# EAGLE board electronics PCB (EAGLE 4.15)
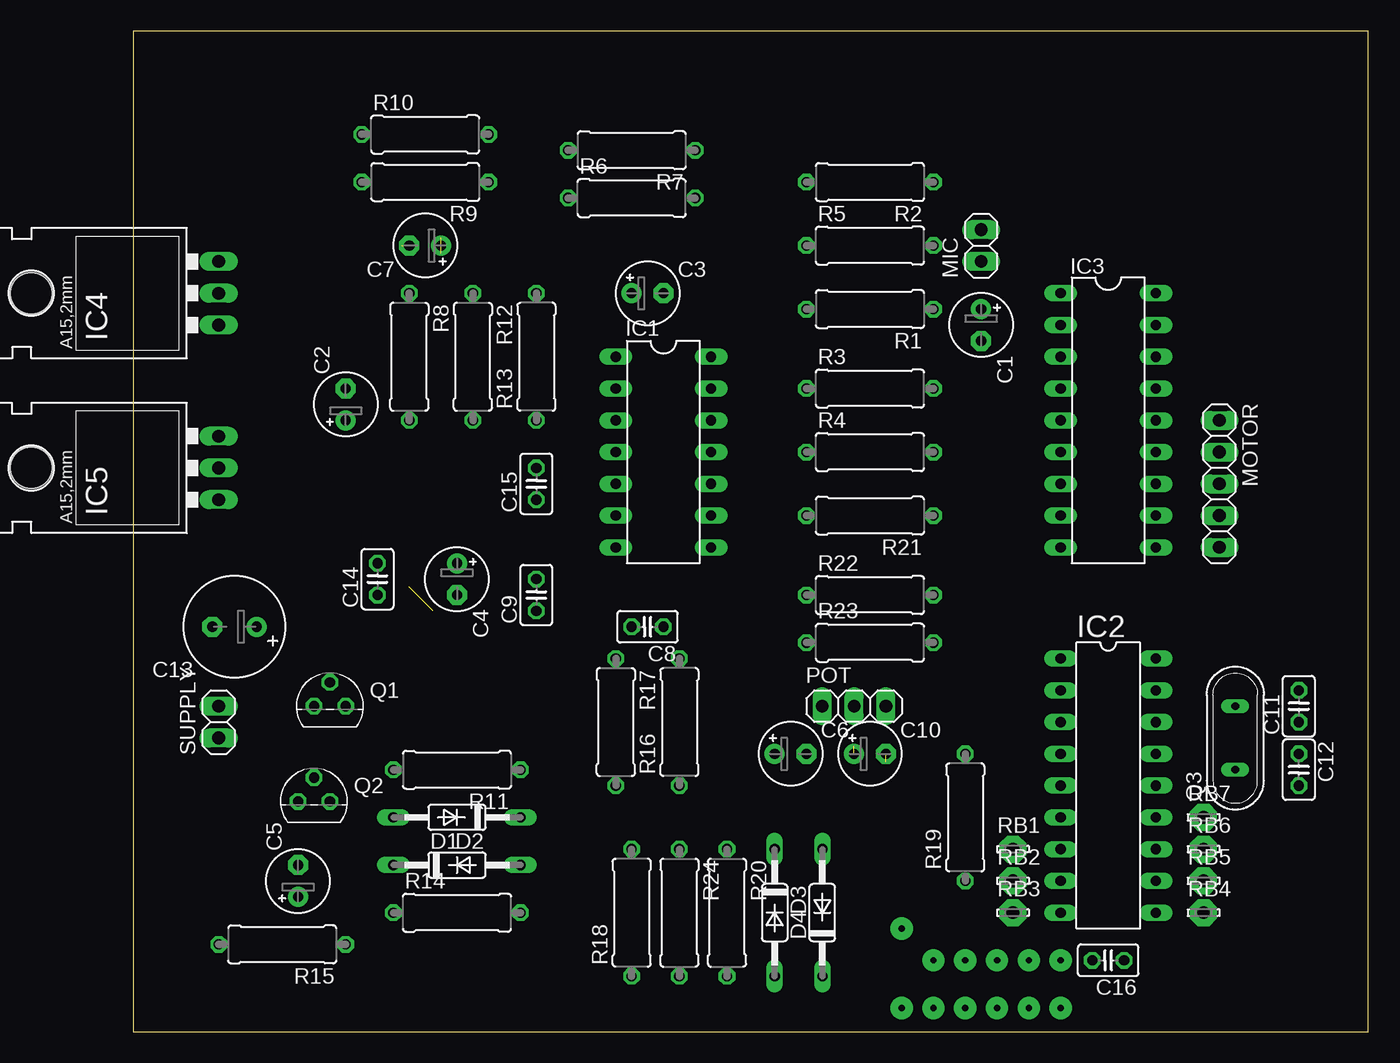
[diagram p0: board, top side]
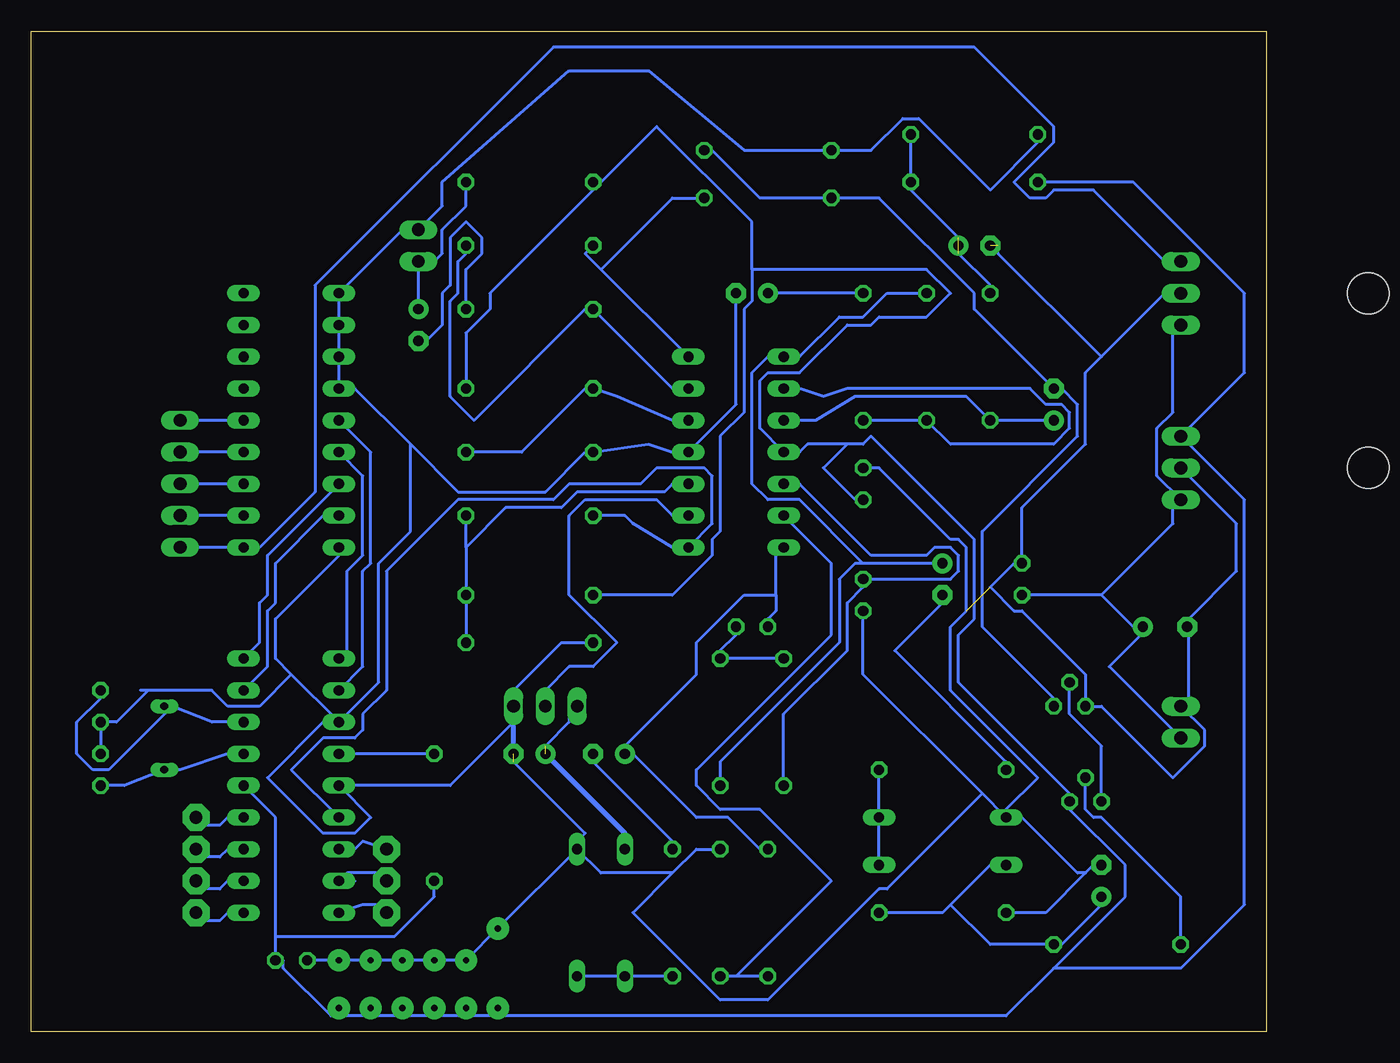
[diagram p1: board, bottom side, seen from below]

Size 98.73 x 80 mm. Coordinates in mm from the lower left corner, seen from the top.
Outline: 0,0 98.73,0 98.73,80 0,80 0,0
Copper layers (1*16): Top 0.035mm / dielectric 1.5mm / Bottom 0.035mm
Design rules "default": minimum track width 10mil, minimum drill 24mil, track to track 8mil, track to pad 8mil, pad to pad 8mil, via to via 8mil, smd to smd 8mil, copper to edge 40mil, drill to drill 8mil, minimum pad ring 10mil, minimum via ring 8mil, stop-mask expansion 4mil, vias tented up to drill 0mil, thermal gap 10mil

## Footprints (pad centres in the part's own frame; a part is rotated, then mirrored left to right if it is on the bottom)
E2,5-5 = drill 0.813 pad 1.6 round: + -1.27,0 | drill 0.813 pad 1.6 octagon: - 1.27,0
C025-025X050 = drill 0.813 octagon: 1 -1.27,0; 2 1.27,0
E3,5-8 = drill 0.813 pad 1.6 round: + -1.778,0 | drill 0.813 pad 1.6 octagon: - 1.778,0
DO35-10 = drill 0.813 long: A 5.08,0; C -5.08,0
DIL14 = drill 0.813 long: 1 -7.62,-3.81; 2 -5.08,-3.81; 3 -2.54,-3.81; 4 0,-3.81; 5 2.54,-3.81; 6 5.08,-3.81; 7 7.62,-3.81; 8 7.62,3.81; 9 5.08,3.81; 10 2.54,3.81; 11 0,3.81; 12 -2.54,3.81; 13 -5.08,3.81; 14 -7.62,3.81
DIL18 = drill 0.813 long: 1 -10.16,-3.81; 2 -7.62,-3.81; 3 -5.08,-3.81; 4 -2.54,-3.81; 5 0,-3.81; 6 2.54,-3.81; 7 5.08,-3.81; 8 7.62,-3.81; 9 10.16,-3.81; 10 10.16,3.81; 11 7.62,3.81; 12 5.08,3.81; 13 2.54,3.81; 14 0,3.81; 15 -2.54,3.81; 16 -5.08,3.81; 17 -7.62,3.81; 18 -10.16,3.81
78XXL = drill 1.016 long: GND 0,-3.81; IN -2.54,-3.81; OUT 2.54,-3.81 | hole 3.302: 0,11.176
1X02 = drill 1.016 long: 1 -1.27,0; 2 1.27,0
1X05 = drill 1.016 long: 1 -5.08,0; 2 -2.54,0; 3 0,0; 4 2.54,0; 5 5.08,0
1X03 = drill 1.016 long: 1 -2.54,0; 2 0,0; 3 2.54,0
TO92 = drill 0.813 octagon: 1 1.27,0; 2 0,1.905; 3 -1.27,0
QS = drill 0.61 long: 1 -2.54,0; 2 2.54,0
0309/10 = drill 0.813 octagon: 1 -5.08,0; 2 5.08,0
LSP10 = drill 1.016 pad 2.159 octagon: MP 0,0

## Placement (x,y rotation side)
C1  4.7u  [E2,5-5]  67.78,56.51 270 top
C2  10u  [E2,5-5]  16.98,50.16 90 top
C3  22u  [E2,5-5]  41.11,59.05 0 top
C4  22u  [E2,5-5]  25.87,36.19 270 top
C5  47u  [E2,5-5]  13.17,12.06 90 top
C6  22u  [E2,5-5]  52.54,22.22 0 top
C7  100u  [E2,5-5]  23.33,62.86 180 top
C8  22n  [C025-025X050]  41.11,32.38 180 top
C9  10n  [C025-025X050]  32.22,34.92 90 top
C10  2.2u  [E2,5-5]  58.89,22.22 0 top
C11  22n  [C025-025X050]  93.18,26.03 90 top
C12  22n  [C025-025X050]  93.18,20.95 270 top
C13  100u/65V  [E3,5-8]  8.09,32.38 180 top
C14  100n  [C025-025X050]  19.52,36.19 90 top
C15  100n  [C025-025X050]  32.22,43.81 90 top
C16  100n  [C025-025X050]  77.94,5.71 180 top
D1  1N4148  [DO35-10]  25.87,13.33 0 top
D2  1N4148  [DO35-10]  25.87,17.14 180 top
D3  1N4148  [DO35-10]  51.27,9.52 270 top
D4  1N4148  [DO35-10]  55.08,9.52 90 top
IC1  LM324N  [DIL14]  42.38,46.35 270 top
IC2  PIC16F84A  [DIL18]  77.94,19.68 270 top
IC3  ULN2803A  [DIL18]  77.94,48.89 270 top
IC4  [78XXL]  3.01,59.05 90 top
IC5  [78XXL]  3.01,45.08 90 top
MIC  [1X02]  67.78,62.86 90 top
MOTOR  [1X05]  86.83,43.81 270 top
POT  [1X03]  57.62,26.03 0 top
Q1  2N3904  [TO92]  15.71,26.03 0 top
Q2  2N3904  [TO92]  14.44,18.41 0 top
Q3  4MHz  [QS]  88.1,23.49 90 top
R1  10k  [0309/10]  58.89,57.78 180 top
R2  2k2  [0309/10]  58.89,67.94 180 top
R3  6k8  [0309/10]  58.89,51.43 0 top
R4  6k8  [0309/10]  58.89,46.35 0 top
R5  var  [0309/10]  58.89,62.86 0 top
R6  180k  [0309/10]  39.84,66.67 0 top
R7  47k  [0309/10]  39.84,70.48 180 top
R8  1M  [0309/10]  22.06,53.97 270 top
R9  100k  [0309/10]  23.33,67.94 180 top
R10  100k  [0309/10]  23.33,71.75 0 top
R11  5k6  [0309/10]  25.87,20.95 180 top
R12  27k  [0309/10]  27.14,53.97 270 top
R13  560  [0309/10]  32.22,53.97 90 top
R14  100k  [0309/10]  25.87,9.52 0 top
R15  10k  [0309/10]  11.9,6.98 180 top
R16  47k  [0309/10]  43.65,24.76 90 top
R17  47k  [0309/10]  38.57,24.76 270 top
R18  5k6  [0309/10]  39.84,9.52 90 top
R19  10k  [0309/10]  66.51,17.14 90 top
R20  560  [0309/10]  47.46,9.52 270 top
R21  270k  [0309/10]  58.89,41.27 180 top
R22  180k  [0309/10]  58.89,34.92 0 top
R23  4k7  [0309/10]  58.89,31.11 0 top
R24  100k  [0309/10]  43.65,9.52 270 top
RB1  LSP10  [LSP10]  70.32,14.6 0 top
RB2  LSP10  [LSP10]  70.32,12.06 0 top
RB3  LSP10  [LSP10]  70.32,9.52 0 top
RB4  LSP10  [LSP10]  85.56,9.52 0 top
RB5  LSP10  [LSP10]  85.56,12.06 0 top
RB6  LSP10  [LSP10]  85.56,14.6 0 top
RB7  LSP10  [LSP10]  85.56,17.14 0 top
SUPPLY  [1X02]  6.82,24.76 90 top

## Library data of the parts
C1-C16 R1-R24 = rcl
D1-D4 = diode
IC1 = linear
IC2 = microchip-2
IC3 = uln-udn
IC4 IC5 = v-reg
MIC MOTOR POT SUPPLY = pinhead
Q1 Q2 = transistor-npn
Q3 = special
RB1-RB7 = solpad

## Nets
+5V: C15.1 C16.1 IC1.4 IC2.14 IC5.OUT Q2.1 R2.2 R3.2 R9.2 R19.1 R22.1
+12V: IC3.10 IC4.OUT MOTOR.5
GND: C3.- C5.- C7.- C9.1 C10.- C11.1 C12.1 C13.- C14.2 C15.2 C16.2 D2.A D4.A IC1.11 IC2.3 IC2.5 IC3.1 IC3.2 IC3.3 IC3.4 IC3.9 IC4.GND IC5.GND MIC.2 POT.3 Q1.3 R4.1 R7.2 R10.1 R14.1 R23.1 R24.1 SUPPLY.2
N$1: C1.+ MIC.1 R2.1
N$2: C7.+ R8.1 R9.1 R10.2
N$3: C3.+ R13.2
N$4: C4.- R11.2
N$5: C8.1 R16.2 R17.1
N$6: IC1.6 R18.1 R24.2
N$7: C1.- R1.1
N$8: IC1.13 R1.2 R5.2
N$9: C4.+ IC1.1 R12.1 R16.1
N$10: IC1.12 R3.1 R4.2
N$11: IC1.14 R5.1 R6.2
N$12: C2.- Q1.1 R6.1 R7.1
N$13: C2.+ IC1.3 R8.2
N$14: C9.2 IC1.5 R17.2
N$15: IC1.2 R12.2 R13.1
N$16: D1.A D2.C R11.1
N$17: C5.+ D1.C R14.2 R15.1
N$18: Q2.2 R15.2
N$19: C6.+ C8.2 IC1.7 R18.2
N$20: Q1.2 Q2.3
N$21: C6.- R20.1
N$22: D3.A D4.C R20.2
N$23: C10.+ D3.C POT.1
N$24: IC1.9 POT.2
N$25: IC1.10 R21.1 R22.2 R23.2
N$26: IC1.8 IC2.6 R21.2
N$27: IC2.7 RB1.MP
N$28: IC2.8 RB2.MP
N$29: IC2.9 RB3.MP
N$30: IC2.10 RB4.MP
N$31: IC2.11 RB5.MP
N$32: IC2.12 RB6.MP
N$33: IC2.13 RB7.MP
N$34: IC2.2 IC3.5
N$35: IC2.1 IC3.6
N$36: IC2.18 IC3.7
N$37: IC2.17 IC3.8
N$38: IC3.11 MOTOR.4
N$39: IC3.12 MOTOR.3
N$40: IC3.13 MOTOR.2
N$41: IC3.14 MOTOR.1
N$42: C11.2 IC2.16 Q3.2
N$43: C12.2 IC2.15 Q3.1
N$45: IC2.4 R19.2
N$46: C13.+ C14.1 IC4.IN IC5.IN SUPPLY.1

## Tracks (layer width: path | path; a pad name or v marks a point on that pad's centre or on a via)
+5V
  Bottom 0.254: 41.11,60.96 41.11,64.77 48.73,72.38 53.18,67.94 R2.2 53.81,67.3 62.07,59.05 62.07,57.78 63.97,55.88 R3.2 | 41.11,60.96 41.11,58.41 41.75,57.78 41.75,49.53 43.65,47.62 43.65,40 44.29,39.37 44.29,38.1 47.46,34.92 R22.1 | R9.2 10.63,67.94 1.74,59.05 1.74,52.7 IC5.OUT 1.74,42.54 1.74,10.16 6.82,5.08 16.98,5.08 | 79.21,7.62 79.21,17.14 IC2.14 | 79.21,7.62 C16.1 78.58,5.71 78.58,5.08 74.77,1.27 20.79,1.27 16.98,5.08 | 79.21,7.62 69.69,7.62 66.51,10.79 R19.1 | 33.49,46.98 36.67,46.98 37.3,46.35 IC1.4 40.48,48.26 40.48,52.07 39.84,52.7 37.3,52.7 33.49,56.51 31.58,56.51 30.95,57.15 27.14,57.15 25.23,59.05 27.14,60.96 41.11,60.96 | 33.49,46.98 32.22,46.98 31.58,47.62 23.33,39.37 23.33,33.02 24.6,31.74 24.6,27.93 15.71,19.04 Q2.1 15.71,17.77 11.26,13.33 11.26,10.79 16.98,5.08 | 33.49,46.98 35.4,45.08 32.86,42.54 C15.1
+12V
  Bottom 0.254: MOTOR.5 IC3.10 80.48,38.73 76.03,43.18 76.03,59.69 56.98,78.73 23.33,78.73 16.98,72.38 16.98,71.11 20.15,67.94 18.88,66.67 17.61,66.67 16.98,67.3 13.8,67.3 8.09,61.59 IC4.OUT
GND  (via drill 0.5 pad 1.78)  (3 unrouted)
  Bottom 0.254: R10.1 18.25,71.11 22.06,67.3 27.77,73.02 29.04,73.02 31.58,70.48 R7.2 41.75,70.48 49.37,76.83 55.72,76.83 65.88,67.94 65.88,66.03 MIC.2 69.05,64.13 IC3.1 IC3.2 IC3.3 IC3.4 72.86,51.43 68.42,46.98 | C3.- 42.38,50.16 IC1.11 47.46,46.35 49.37,46.98 R4.1 54.45,46.35 57.62,43.18 64.61,43.18 68.42,46.98 | C12.1 C11.1 91.91,24.76 89.37,27.3 | 89.37,27.3 90.01,27.3 | 89.37,27.3 84.29,27.3 83.02,26.03 80.48,26.03 77.94,28.57 | IC3.9 74.13,38.1 79.21,33.02 79.21,29.84 77.94,28.57 | 68.42,46.98 68.42,40 70.95,37.46 70.95,27.93 IC2.3 | IC2.3 77.94,28.57 | IC5.GND 2.38,40.64 2.38,36.83 6.19,33.02 C13.- 6.19,31.74 6.19,26.66 SUPPLY.2 4.92,24.12 4.92,22.86 7.46,20.31 13.17,26.03 Q1.3 14.44,28.57 19.52,33.65 20.15,33.65 22.06,35.55 20.15,37.46 C14.2 19.52,41.91 14.44,46.98 14.44,52.7 13.17,53.97 | IC2.3 75.4,24.76 79.84,20.31 75.4,15.87 72.86,15.87 71.59,17.14 IC2.5 65.24,19.68 60.16,24.76 POT.3 60.16,27.3 56.35,31.11 R23.1 | C16.2 v74.13,5.71 v71.59,5.71 v69.05,5.71 v66.51,5.71 v63.97,5.71 v61.43,8.25 D4.A | 21.43,62.86 21.43,62.23 13.17,53.97 | IC4.GND 8.09,59.05 13.17,53.97 | 60.16,21.58 54.45,15.87 55.08,15.24 D4.A | C15.2 30.95,45.08 25.23,39.37 24.6,39.37 23.96,38.73 23.96,33.65 25.23,32.38 25.23,27.3 18.25,20.31 20.79,17.77 D2.A | D4.A 53.18,12.7 47.46,12.7 | R24.1 45.55,14.6 47.46,12.7 | 47.46,12.7 50.64,9.52 43.65,2.54 39.84,2.54 30.95,11.43 30.31,11.43 22.7,19.04 | C9.1 32.22,28.57 22.7,19.04 | D2.A 22.7,19.04 | D2.A 19.52,17.14 15.07,12.7 14.44,12.7 | R14.1 17.61,9.52 14.44,12.7 | 14.44,12.7 13.8,13.33 C5.-
  Bottom 0.406: C10.- 60.16,24.76
N$1
  Bottom 0.254: R2.1 63.97,66.03 65.88,64.13 65.88,62.23 66.51,61.59 MIC.1 C1.+
N$2  (2 unrouted)
  Bottom 0.254: R10.2 R9.1 28.41,67.3 24.6,63.5 | 24.6,62.23 22.06,59.69 R8.1
N$3
  Bottom 0.254: R13.2 C3.+
N$4
  Bottom 0.254: R11.2 20.79,21.58 29.68,30.47 25.87,34.29 C4.-
N$5
  Bottom 0.254: R17.1 R16.2 43.65,30.47 42.38,31.74 C8.1
N$6
  Bottom 0.254: R18.1 42.38,4.44 | 42.38,4.44 R24.2 | 42.38,4.44 34.76,12.06 40.48,17.77 43.65,17.77 45.55,19.68 45.55,20.95 34.76,31.74 34.76,37.46 IC1.6
N$7
  Bottom 0.254: R1.1 63.97,60.96 62.7,62.23 62.7,63.5 63.97,64.77 65.24,63.5 65.24,59.69 65.88,59.05 65.88,56.51 67.14,55.24 C1.-
N$8
  Bottom 0.254: IC1.13 47.46,51.43 R1.2 54.45,57.78 63.34,48.89 65.24,50.8 65.24,58.41 64.61,59.05 64.61,61.59 63.97,62.23 R5.2
N$9
  Bottom 0.254: R12.1 30.31,59.05 32.22,57.15 34.12,57.15 37.3,53.97 IC1.1 39.84,53.97 41.11,52.7 41.11,43.81 39.84,42.54 37.3,42.54 32.22,37.46 | 32.22,37.46 32.86,37.46 34.12,36.19 34.12,31.11 43.65,21.58 R16.1 | C4.+ 32.22,37.46
N$10
  Bottom 0.254: IC1.12 47.46,48.89 51.91,50.8 R3.1 54.45,51.43 59.53,46.35 R4.2
N$11
  Bottom 0.254: 53.18,60.96 54.45,62.23 R5.1 | IC1.14 53.18,60.96 | 53.18,60.96 47.46,66.67 R6.2
N$12
  Bottom 0.254: R7.1 44.29,70.48 40.48,66.67 R6.1 30.95,66.67 23.33,59.05 23.33,57.78 C2.- 16.34,51.43 15.07,50.16 15.07,47.62 22.7,40 22.7,32.38 16.98,26.66 Q1.1
N$13
  Bottom 0.254: C2.+ R8.2 23.96,50.8 32.86,50.8 36.03,48.89 IC1.3
N$14
  Bottom 0.254: R17.2 38.57,25.39 33.49,30.47 33.49,34.29 32.22,35.55 C9.2 25.23,36.19 24.6,36.83 24.6,38.1 25.23,38.73 26.5,38.73 27.14,38.1 31.58,38.1 37.3,43.81 IC1.5
N$15
  Bottom 0.254: R13.1 R12.2 25.23,46.98 16.98,46.98 15.71,48.26 15.71,49.53 16.34,50.16 17.61,50.16 18.88,51.43 33.49,51.43 35.4,50.8 37.3,51.43 IC1.2
N$16
  Bottom 0.254: D1.A D2.C R11.1
N$17
  Bottom 0.254: C5.+ 13.17,10.16 16.34,6.98 R15.1 22.06,6.98 25.23,10.16 | 25.23,10.16 22.06,13.33 D1.C | 25.23,10.16 25.87,9.52 R14.2
N$18
  Bottom 0.254: R15.2 6.82,10.79 13.17,17.14 13.8,17.14 14.44,17.77 Q2.2
N$19
  Bottom 0.254: 39.21,34.92 39.21,33.65 39.84,33.02 C8.2 | 39.21,34.92 39.21,38.1 IC1.7 | R18.2 40.48,14.6 43.02,17.14 45.55,17.14 50.64,22.22 C6.+ 51.27,22.86 45.55,28.57 45.55,31.11 41.75,34.92 39.21,34.92
N$20
  Bottom 0.254: Q2.3 13.17,22.86 15.71,25.39 Q1.2
N$21
  Bottom 0.254: R20.1 47.46,15.24 53.81,21.58 C6.-
N$22
  Bottom 0.254: R20.2 D3.A D4.C
N$23  (1 unrouted)
  Bottom 0.254: D3.C 51.27,15.87 | 57.62,22.86 55.72,24.76 55.72,25.39 POT.1
  Bottom 0.406: 51.27,15.87 C10.+
N$24
  Bottom 0.254: IC1.9 47.46,41.27 48.73,42.54 54.45,42.54 55.72,41.27 55.72,34.92 51.91,31.11 53.81,29.2 55.72,29.2 57.62,27.3 POT.2
N$25
  Bottom 0.254: R23.2 R22.2 63.97,38.73 | 63.97,38.73 R21.1 | 63.97,38.73 60.8,41.91 56.35,41.91 55.08,43.18 48.1,43.18 47.46,43.81 IC1.10
N$26
  Bottom 0.254: R21.2 51.27,41.27 50.64,40.64 47.46,38.73 IC1.8 44.29,40.64 44.29,44.45 44.92,45.08 48.73,45.08 50,43.81 55.72,43.81 56.98,42.54 64.61,42.54 70.32,36.83 70.32,27.3 72.23,25.39 72.23,24.12 72.86,23.49 75.4,23.49 77.94,20.95 IC2.6
N$27
  Bottom 0.254: IC2.7 72.86,14.6 72.23,15.24 RB1.MP
N$28
  Bottom 0.254: IC2.8 72.86,12.06 73.5,12.7 70.95,12.7 RB2.MP
N$29
  Bottom 0.254: IC2.9 72.23,10.16 70.95,10.16 RB3.MP
N$30
  Bottom 0.254: IC2.10 83.02,9.52 83.66,8.89 84.92,8.89 RB4.MP
N$31
  Bottom 0.254: IC2.11 83.02,12.06 83.66,11.43 84.92,11.43 RB5.MP
N$32
  Bottom 0.254: IC2.12 83.02,14.6 83.66,13.97 84.92,13.97 RB6.MP
N$33
  Bottom 0.254: IC2.13 83.02,17.14 83.66,16.5 84.92,16.5 RB7.MP
N$34
  Bottom 0.254: IC2.2 72.23,29.2 72.23,36.83 71.59,37.46 71.59,46.35 IC3.5
N$35
  Bottom 0.254: IC2.1 73.5,30.47 73.5,36.83 72.23,38.1 72.23,44.45 IC3.6
N$36
  Bottom 0.254: IC3.7 79.84,38.1 79.84,34.92 80.48,34.29 80.48,31.11 IC2.18
N$37
  Bottom 0.254: IC2.17 79.84,29.2 79.84,33.65 79.21,34.29 79.21,37.46 75.4,41.27 IC3.8
N$38
  Bottom 0.254: IC3.11 MOTOR.4
N$39
  Bottom 0.254: IC3.12 MOTOR.3
N$40
  Bottom 0.254: IC3.13 MOTOR.2
N$41
  Bottom 0.254: IC3.14 MOTOR.1
N$42
  Bottom 0.254: 87.47,26.03 84.29,24.76 IC2.16 | 87.47,26.03 92.55,20.95 93.81,20.95 95.09,22.22 95.09,24.76 93.18,26.66 C11.2 | 87.47,26.03 Q3.2
N$43
  Bottom 0.254: C12.2 91.28,19.68 Q3.1 86.83,20.95 83.02,22.22 IC2.15
N$44  (via drill 0.5 pad 1.78)
  other vias: 61.43,1.9
N$45
  Bottom 0.254: R19.2 IC2.4
N$46
  Bottom 0.254: 13.17,34.92 10.63,32.38 C13.+ 9.99,31.74 12.54,29.2 SUPPLY.1 | 13.17,34.92 C14.1 | 13.17,34.92 7.46,40.64 7.46,41.91 IC5.IN 8.72,44.45 8.72,48.26 7.46,49.53 7.46,55.88 IC4.IN
N$47  (via drill 0.5 pad 1.78)
  other vias: 63.97,1.9
N$48  (via drill 0.5 pad 1.78)
  other vias: 66.51,1.9
N$49  (via drill 0.5 pad 1.78)
  other vias: 69.05,1.9
N$50  (via drill 0.5 pad 1.78)
  other vias: 71.59,1.9
N$51  (via drill 0.5 pad 1.78)
  other vias: 74.13,1.9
